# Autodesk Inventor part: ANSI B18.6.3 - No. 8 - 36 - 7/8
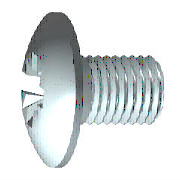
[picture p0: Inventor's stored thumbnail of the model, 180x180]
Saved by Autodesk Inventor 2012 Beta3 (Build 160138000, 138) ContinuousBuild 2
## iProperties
Created: 2010-12
Part Number: ANSI B18.6.3 - No. 8 - 36 - 7/8
Material: Steel, Mild
Description: Cross Recessed Truss Head Machine Screw - Type IA
Document SubType Name: Modeling
Standard: ANSI B18.6.3
Designer: Beta-8540w
Standard Revision: 2003
Standards Organization: ANSI
Language: en-US
Size Designation: No. 8 - 36 - 7/8
Categories: <MemberInstance><Categories><Category DisplayName="Fasteners" InternalName="e4da775c-781d-43d5-af7c-5136215cf5a6" Mnemonic="FSTN"><Category DisplayName="Bolts"
Density: 1 g/cm^3
IsCustomPart: 0
Author: Beta-8540w
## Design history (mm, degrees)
body "Solid1"
workplane "Work Plane3"
sketch "Sketch4"
  geometry: L1 (-9, 0)-(9, 0) reference; L2 (0, -9)-(0, 9) reference; L3 (0, 0)-(6.428, 6.428); L4 (0, 0)-(6.428, -6.428); L5 (0, 0)-(-6.428, 6.428); L6 (0, 0)-(-6.428, -6.428); L7 (1.392, 1.392)-(0, 0.26); L8 (-1.392, 1.392)-(-0.26, 0); L9 (-1.392, -1.392)-(0, -0.26); L10 (1.392, -1.392)-(0.26, 0); L11 (1.392, 1.392)-(0.26, 0); L12 (-1.392, 1.392)-(0, 0.26); L13 (-1.392, -1.392)-(-0.26, 0); L14 (1.392, -1.392)-(0, -0.26); C1 r 4.877 at (0, 0) reference; A1 r 0.26 centre (0, 0) between (0, 0.26) and (0, -0.26); A2 r 1.968 centre (0, 0) between (1.392, 1.392) and (1.392, -1.392); 1 further point
  constraints: 25 end point, 7 point on circle, 7 point on line, 3 symmetric about line, 2 centre point, 2 coincident, 2 perpendicular, 3 other
  dimensions: "d11" = 0.5207 diameter of A1 (= 0.5 x SBR); "d14" = 45 deg angle of L3 L1; "d29" = 1.39194 distance from line of L1 L7.start (= 0.353553 x SDM)
extrude "Star Cut" cut sketch "Sketch4" distance "d12" = 2.5908 (= KOH); taper "d13" = -30 deg
sketch "Sketch2"
  geometry: L1 (-7.196, 0)-(9.04, 0) reference; L2 (0, -7.196)-(0, 9.04) reference; L3 (0, 1.969)-(0, 0); L4 (0, 0)-(1.968, 0); L5 (0, 0)-(6.721, 6.721); L6 (0.521, 1.898)-(0.297, 0.938); L7 (1.898, 0.521)-(0.938, 0.297); L8 (1.898, -0.521)-(0.938, -0.297); L9 (0.521, -1.898)-(0.297, -0.938); L10 (-0.521, 1.898)-(-0.297, 0.938); L11 (-1.898, 0.521)-(-0.938, 0.297); L12 (-0.521, -1.898)-(-0.297, -0.938); L13 (-1.898, -0.521)-(-0.938, -0.297); C1 r 4.877 at (0, 0) reference; A1 r 0.787 centre (0, 0) between (0.787, 0) and (0, 0.787); A2 r 0.245 centre (0.536, 0.883) between (0.297, 0.938) and (0.709, 0.709); A3 r 0.245 centre (0.883, 0.536) between (0.709, 0.709) and (0.938, 0.297); A4 r 1.968 centre (0, 0) between (1.968, 0) and (1.898, 0.521); A5 r 1.968 centre (0, 0) between (0.521, 1.898) and (0, 1.969); A6 r 1.968 centre (0, 0) between (1.898, 0.521) and (0.521, 1.898); A7 r 1.968 centre (0, 0) between (0, -1.969) and (0.521, -1.898); A8 r 1.968 centre (0, 0) between (0.521, -1.898) and (1.898, -0.521); A9 r 1.968 centre (0, 0) between (1.898, -0.521) and (1.968, 0); A10 r 0.245 centre (0.536, -0.883) between (0.709, -0.709) and (0.297, -0.938); A11 r 0.245 centre (0.883, -0.536) between (0.938, -0.297) and (0.709, -0.709); A12 r 0.245 centre (-0.536, 0.883) between (-0.709, 0.709) and (-0.297, 0.938); A13 r 0.245 centre (-0.883, 0.536) between (-0.938, 0.297) and (-0.709, 0.709); A14 r 1.968 centre (0, 0) between (-1.898, 0.521) and (-1.968, 0); A15 r 1.968 centre (0, 0) between (-0.521, 1.898) and (-1.898, 0.521); A16 r 1.968 centre (0, 0) between (0, 1.969) and (-0.521, 1.898); A17 r 1.968 centre (0, 0) between (-1.968, 0) and (-1.898, -0.521); A18 r 1.968 centre (0, 0) between (-1.898, -0.521) and (-0.521, -1.898); A19 r 1.968 centre (0, 0) between (-0.521, -1.898) and (0, -1.969); A20 r 0.245 centre (-0.883, -0.536) between (-0.709, -0.709) and (-0.938, -0.297); A21 r 0.245 centre (-0.536, -0.883) between (-0.297, -0.938) and (-0.709, -0.709); A22 r 0.984 centre (0, 0) between (0.984, 0) and (0, 0.984)
  constraints: 46 point on circle, 25 symmetric about line, 22 centre point, 22 end point, 6 tangent, 4 coincident, 3 collinear, 3 point on line, 1 midpoint, 1 perpendicular, 22 other
  dimensions: "d4" = 45 deg angle of L5 L4; "d5" = 1.5748 diameter of A1 (= 0.4 x SDM); "d6" = 3.937 diameter of A6 (= SDM); "d7" = 0.5207 distance from line of L6.start L3 (= 0.5 x SBR); "d20" = 1.9685 diameter of A22 (= 0.5 x SDM)
extrude "Slot" join sketch "Sketch2" taper "d21" = 0 deg; stored distance "d54" = 10
revolve "Cut" stored, may be unused: angle "d56" = 90 deg
revolve "Body" stored, may be unused: angle "d18" = 90 deg
node "IDS_WORKPLANE{1}"
sketch "Sketch1"
  geometry: L1 (22.225, 0)-(22.225, 2.083); L2 (22.225, 2.083)-(0, 2.083); L3 (3.962, 5.08)-(3.962, 5.08); L4 (-2.591, 0)-(-2.591, 4.877); L5 (-2.324, 1.836)-(-1.077, 1.214); L6 (-1.077, 1.214)-(-0.432, 0); L7 (-0.432, 0)-(22.225, 0); L8 (-8.191, 0)-(27.294, 0) reference; L9 (0, -1.024)-(0, 6.143) reference; L10 (-2.324, 1.836)-(-2.591, 1.968); L11 (-0.363, 4.877)-(-2.591, 4.877); L12 (-0.363, 4.877)-(0, 4.877); L13 (0, 4.877)-(0, 2.083); A1 r 6.452 centre (3.861, 0) between (-0.363, 4.877) and (-2.591, 0)
  constraints: 22 end point, 4 collinear, 4 point on circle, 3 point on line, 2 parallel, 2 perpendicular, 1 centre point, 1 horizontal, 1 tangent
  dimensions: "d1" = 4.1656 diameter of L2 L7 (= GD); "d2" = 2.159 distance from line of L6.end L4 (= STI); "d16" = 3.937 diameter of L10.end L7 (= SDM); "d17" = 62 deg angle of L6 L7; "d19" = 26.5 deg angle of L5 L7; "d23" = 9.7536 diameter of L12.end L7 (= KOD); "d25" = 2.5908 distance between parallel lines of L4 L13 (= KOH); "d26" = 6.4516 radius of A1 (= KR); "d28" = 22.225 distance between parallel lines of L1 L13 (= NLG)
fillet "Fillet1" dims "d22" = 0.20828 (= 0.2 x SBR)
feature "Thread" dims "d8" = 20.46122 (= GEL), "d9" = 0
chamfer "Chamfer" distance "d78" = 0.35278 (= 0.5 x RR); stored, may be unused: second distance "d79" = 2, angle "d80" = 45 deg
other parameters: "GD" = 4.1656 (= NND) [user parameter; used in 1 equation term], "NLG" = 22.225 [user parameter; used in 1 equation term], "GEL" = 20.46122 [user parameter; used in 1 equation term], "KOD" = 9.7536 [user parameter; used in 1 equation term], "KOH" = 2.5908 [user parameter; used in 3 equation terms], "SDM" = 3.937 [user parameter; used in 5 equation terms], "STI" = 2.159 [user parameter; used in 1 equation term], "SBR" = 1.0414 [user parameter; used in 3 equation terms], "d3" = -2.5908 (= -KOH), "d10" = 0, "KR" = 6.4516 [user parameter; used in 1 equation term], "d75" = 0, "d76" = 0, "RR" = 0.70556 (computed from TPU) [user parameter; used in 1 equation term], "GUL" = 0 [user parameter], "SPD" = 3.40106 [user parameter], "PTC" = 0.70556 (computed from TPU) [user parameter], "THREADDIA" = 4.1656 [user parameter], "TOA" = 30 deg [user parameter], "BDM" = 4.1656 (= NND) [user parameter], "NND" = 4.1656 [user parameter; used in 2 equation terms], "GAL" = 0.70612 [user parameter], "GD1" = 3.40106 [user parameter]
